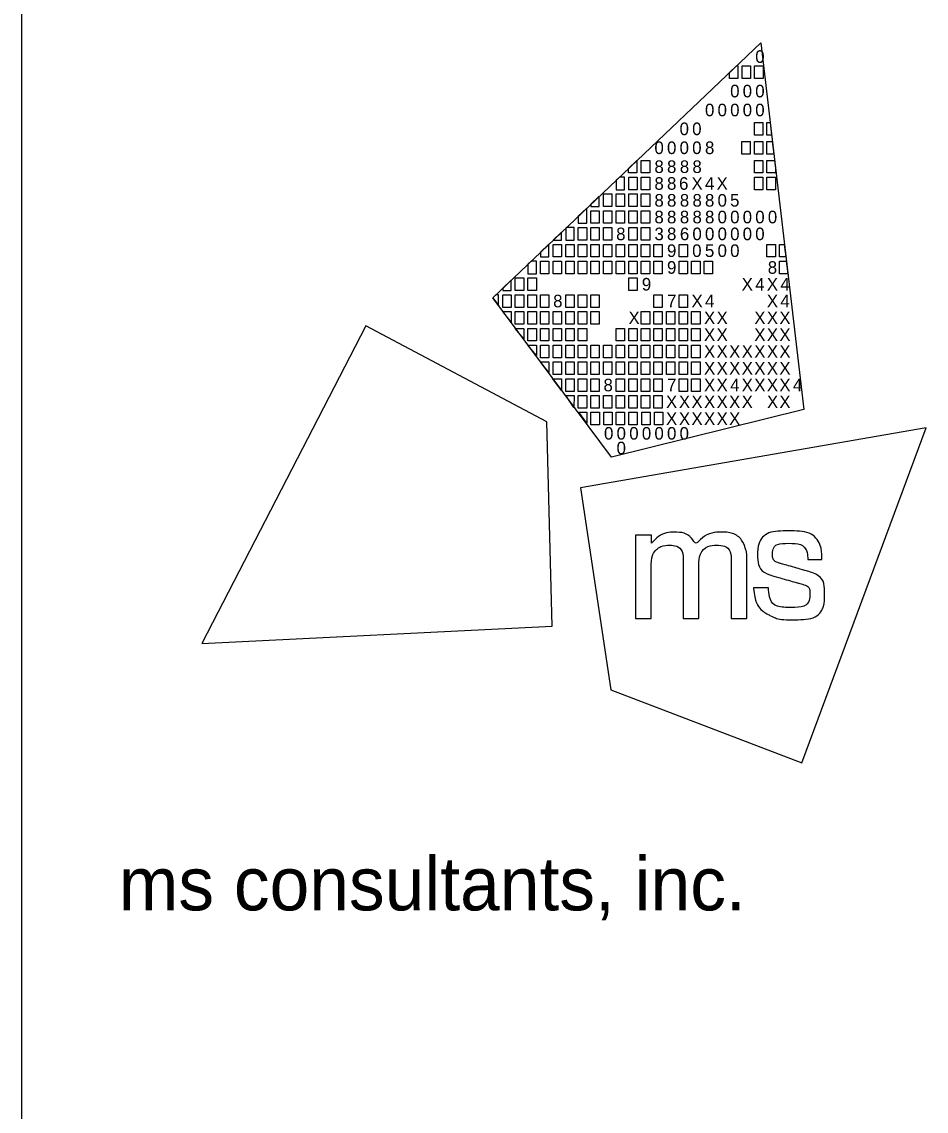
# Model space of a CAD drawing. Extents: x 0 to 34, y 0 to 22.
# Drawn here: x 32 to 33.186, y 2.686 to 4.114 of the extents above; entities that cross this region are included whole.
import ezdxf

# ---------------------------------------------------------------- set-up
doc = ezdxf.new("R2010")
doc.units = 0
doc.layers.add('SH_Border', color=7, linetype='Continuous')
doc.layers.add('SH_Data', color=7, linetype='Continuous')

msp = doc.modelspace()

# ---------------------------------------------------------------- linework, layer by layer
at = {"layer": 'SH_Border'}
for p, q in [((32, 0.5), (32, 21.5)), ((32.6175, 3.7519), (32.9688, 4.0861)), ((32.9688, 4.0861), (32.9688, 4.0861)), ((32.9688, 4.0861), (33.0253, 3.6052)), ((32.773, 3.543), (32.6175, 3.7519)), ((33.0253, 3.6052), (32.773, 3.543))]:
    msp.add_line(p, q, dxfattribs=at)
for points in [[(32.9279, 4.0472), (32.9369, 4.0558), (32.9389, 4.0558), (32.9389, 4.0393), (32.9279, 4.0393)], [(32.9444, 4.0558), (32.9554, 4.0558), (32.9554, 4.0393), (32.9444, 4.0393)], [(32.9609, 4.0558), (32.9719, 4.0558), (32.9719, 4.0393), (32.9609, 4.0393)], [(32.9606, 3.9815), (32.9716, 3.9815), (32.9716, 3.965), (32.9606, 3.965)], [(32.9771, 3.9815), (32.9811, 3.9815), (32.983, 3.965), (32.9771, 3.965)], [(32.9441, 3.9567), (32.9551, 3.9567), (32.9551, 3.9402), (32.9441, 3.9402)], [(32.9606, 3.9567), (32.9716, 3.9567), (32.9716, 3.9402), (32.9606, 3.9402)], [(32.9771, 3.9567), (32.984, 3.9567), (32.9859, 3.9402), (32.9771, 3.9402)], [(32.7953, 3.9211), (32.8064, 3.9316), (32.8064, 3.9154), (32.7953, 3.9154)], [(32.8123, 3.9319), (32.8233, 3.9319), (32.8233, 3.9154), (32.8123, 3.9154)], [(32.9606, 3.9319), (32.9716, 3.9319), (32.9716, 3.9154), (32.9606, 3.9154)], [(32.9771, 3.9319), (32.9869, 3.9319), (32.9881, 3.9218), (32.9881, 3.9154), (32.9771, 3.9154)], [(32.7958, 3.9099), (32.8068, 3.9099), (32.8068, 3.8934), (32.7958, 3.8934)], [(32.8123, 3.9099), (32.8233, 3.9099), (32.8233, 3.8934), (32.8123, 3.8934)], [(32.9606, 3.9099), (32.9716, 3.9099), (32.9716, 3.8934), (32.9606, 3.8934)], [(32.9771, 3.9099), (32.9881, 3.9099), (32.9881, 3.8934), (32.9771, 3.8934)], [(32.7627, 3.8879), (32.7737, 3.8879), (32.7737, 3.8714), (32.7627, 3.8714)], [(32.7793, 3.8879), (32.7903, 3.8879), (32.7903, 3.8714), (32.7793, 3.8714)], [(32.7958, 3.8879), (32.8068, 3.8879), (32.8068, 3.8714), (32.7958, 3.8714)], [(32.8123, 3.8879), (32.8233, 3.8879), (32.8233, 3.8714), (32.8123, 3.8714)], [(32.7462, 3.8659), (32.7572, 3.8659), (32.7572, 3.8494), (32.7462, 3.8494)], [(32.7627, 3.8659), (32.7737, 3.8659), (32.7737, 3.8494), (32.7627, 3.8494)], [(32.7793, 3.8659), (32.7903, 3.8659), (32.7903, 3.8494), (32.7793, 3.8494)], [(32.7958, 3.8659), (32.8068, 3.8659), (32.8068, 3.8494), (32.7958, 3.8494)], [(32.8123, 3.8659), (32.8233, 3.8659), (32.8233, 3.8494), (32.8123, 3.8494)], [(32.7297, 3.8439), (32.7407, 3.8439), (32.7407, 3.8273), (32.7297, 3.8273)], [(32.7462, 3.8439), (32.7572, 3.8439), (32.7572, 3.8273), (32.7462, 3.8273)], [(32.7627, 3.8439), (32.7737, 3.8439), (32.7737, 3.8273), (32.7627, 3.8273)], [(32.7958, 3.8439), (32.8068, 3.8439), (32.8068, 3.8273), (32.7958, 3.8273)], [(32.8123, 3.8439), (32.8233, 3.8439), (32.8233, 3.8273), (32.8123, 3.8273)], [(32.6967, 3.8218), (32.7077, 3.8218), (32.7077, 3.8053), (32.6967, 3.8053)], [(32.7132, 3.8218), (32.7242, 3.8218), (32.7242, 3.8053), (32.7132, 3.8053)], [(32.7297, 3.8218), (32.7407, 3.8218), (32.7407, 3.8053), (32.7297, 3.8053)], [(32.7462, 3.8218), (32.7572, 3.8218), (32.7572, 3.8053), (32.7462, 3.8053)], [(32.7627, 3.8218), (32.7737, 3.8218), (32.7737, 3.8053), (32.7627, 3.8053)], [(32.7793, 3.8218), (32.7903, 3.8218), (32.7903, 3.8053), (32.7793, 3.8053)], [(32.7958, 3.8218), (32.8068, 3.8218), (32.8068, 3.8053), (32.7958, 3.8053)], [(32.8123, 3.8218), (32.8233, 3.8218), (32.8233, 3.8053), (32.8123, 3.8053)], [(32.8288, 3.8218), (32.8398, 3.8218), (32.8398, 3.8053), (32.8288, 3.8053)], [(32.8618, 3.8218), (32.8728, 3.8218), (32.8728, 3.8053), (32.8618, 3.8053)], [(32.9771, 3.8218), (32.9881, 3.8218), (32.9881, 3.8053), (32.9771, 3.8053)], [(32.9935, 3.8218), (32.9998, 3.8218), (33.0018, 3.8053), (32.9935, 3.8053)], [(32.6802, 3.7998), (32.6912, 3.7998), (32.6912, 3.7833), (32.6802, 3.7833)], [(32.6967, 3.7998), (32.7077, 3.7998), (32.7077, 3.7833), (32.6967, 3.7833)], [(32.7132, 3.7998), (32.7242, 3.7998), (32.7242, 3.7833), (32.7132, 3.7833)], [(32.7297, 3.7998), (32.7407, 3.7998), (32.7407, 3.7833), (32.7297, 3.7833)], [(32.7462, 3.7998), (32.7572, 3.7998), (32.7572, 3.7833), (32.7462, 3.7833)], [(32.7627, 3.7998), (32.7737, 3.7998), (32.7737, 3.7833), (32.7627, 3.7833)], [(32.7793, 3.7998), (32.7903, 3.7998), (32.7903, 3.7833), (32.7793, 3.7833)], [(32.7958, 3.7998), (32.8068, 3.7998), (32.8068, 3.7833), (32.7958, 3.7833)], [(32.8123, 3.7998), (32.8233, 3.7998), (32.8233, 3.7833), (32.8123, 3.7833)], [(32.8288, 3.7998), (32.8398, 3.7998), (32.8398, 3.7833), (32.8288, 3.7833)], [(32.8618, 3.7998), (32.8728, 3.7998), (32.8728, 3.7833), (32.8618, 3.7833)], [(32.8783, 3.7998), (32.8893, 3.7998), (32.8893, 3.7833), (32.8783, 3.7833)], [(32.8947, 3.7998), (32.9057, 3.7998), (32.9057, 3.7833), (32.8947, 3.7833)], [(32.9935, 3.7998), (33.0024, 3.7998), (33.0044, 3.7833), (32.9935, 3.7833)], [(32.6471, 3.7778), (32.6581, 3.7778), (32.6581, 3.7613), (32.6471, 3.7613)], [(32.6637, 3.7778), (32.6747, 3.7778), (32.6747, 3.7613), (32.6637, 3.7613)], [(32.7958, 3.7778), (32.8068, 3.7778), (32.8068, 3.7613), (32.7958, 3.7613)], [(32.6306, 3.7558), (32.6416, 3.7558), (32.6416, 3.7393), (32.6306, 3.7393)], [(32.6471, 3.7558), (32.6581, 3.7558), (32.6581, 3.7393), (32.6471, 3.7393)], [(32.6637, 3.7558), (32.6747, 3.7558), (32.6747, 3.7393), (32.6637, 3.7393)], [(32.6802, 3.7558), (32.6912, 3.7558), (32.6912, 3.7393), (32.6802, 3.7393)], [(32.7132, 3.7558), (32.7242, 3.7558), (32.7242, 3.7393), (32.7132, 3.7393)], [(32.7297, 3.7558), (32.7407, 3.7558), (32.7407, 3.7393), (32.7297, 3.7393)], [(32.7462, 3.7558), (32.7572, 3.7558), (32.7572, 3.7393), (32.7462, 3.7393)], [(32.8288, 3.7558), (32.8398, 3.7558), (32.8398, 3.7393), (32.8288, 3.7393)], [(32.8618, 3.7558), (32.8728, 3.7558), (32.8728, 3.7393), (32.8618, 3.7393)], [(32.6306, 3.7338), (32.6416, 3.7338), (32.6416, 3.72)], [(32.6471, 3.7338), (32.6581, 3.7338), (32.6581, 3.7173), (32.6471, 3.7173)], [(32.6637, 3.7338), (32.6747, 3.7338), (32.6747, 3.7173), (32.6637, 3.7173)], [(32.6802, 3.7338), (32.6912, 3.7338), (32.6912, 3.7173), (32.6802, 3.7173)], [(32.6967, 3.7338), (32.7077, 3.7338), (32.7077, 3.7173), (32.6967, 3.7173)], [(32.7132, 3.7338), (32.7242, 3.7338), (32.7242, 3.7173), (32.7132, 3.7173)], [(32.7297, 3.7338), (32.7407, 3.7338), (32.7407, 3.7173), (32.7297, 3.7173)], [(32.7462, 3.7338), (32.7572, 3.7338), (32.7572, 3.7173), (32.7462, 3.7173)], [(32.8123, 3.7338), (32.8233, 3.7338), (32.8233, 3.7173), (32.8123, 3.7173)], [(32.8288, 3.7338), (32.8398, 3.7338), (32.8398, 3.7173), (32.8288, 3.7173)], [(32.8453, 3.7338), (32.8563, 3.7338), (32.8563, 3.7173), (32.8453, 3.7173)], [(32.8618, 3.7338), (32.8728, 3.7338), (32.8728, 3.7173), (32.8618, 3.7173)], [(32.8783, 3.7338), (32.8893, 3.7338), (32.8893, 3.7173), (32.8783, 3.7173)], [(32.6471, 3.7117), (32.6581, 3.7117), (32.6581, 3.698)], [(32.6637, 3.7117), (32.6747, 3.7117), (32.6747, 3.6952), (32.6637, 3.6952)], [(32.6802, 3.7117), (32.6912, 3.7117), (32.6912, 3.6952), (32.6802, 3.6952)], [(32.6967, 3.7117), (32.7077, 3.7117), (32.7077, 3.6952), (32.6967, 3.6952)], [(32.7132, 3.7117), (32.7242, 3.7117), (32.7242, 3.6952), (32.7132, 3.6952)], [(32.7297, 3.7117), (32.7407, 3.7117), (32.7407, 3.6952), (32.7297, 3.6952)], [(32.7793, 3.7117), (32.7903, 3.7117), (32.7903, 3.6952), (32.7793, 3.6952)], [(32.7958, 3.7117), (32.8068, 3.7117), (32.8068, 3.6952), (32.7958, 3.6952)], [(32.8123, 3.7117), (32.8233, 3.7117), (32.8233, 3.6952), (32.8123, 3.6952)], [(32.8288, 3.7117), (32.8398, 3.7117), (32.8398, 3.6952), (32.8288, 3.6952)], [(32.8453, 3.7117), (32.8563, 3.7117), (32.8563, 3.6952), (32.8453, 3.6952)], [(32.8618, 3.7117), (32.8728, 3.7117), (32.8728, 3.6952), (32.8618, 3.6952)], [(32.8783, 3.7117), (32.8893, 3.7117), (32.8893, 3.6952), (32.8783, 3.6952)], [(32.6637, 3.6897), (32.6747, 3.6897), (32.6747, 3.676)], [(32.6747, 3.6897), (32.6747, 3.6897), (32.6747, 3.6897)], [(32.6802, 3.6897), (32.6912, 3.6897), (32.6912, 3.6732), (32.6802, 3.6732)], [(32.6967, 3.6897), (32.7077, 3.6897), (32.7077, 3.6732), (32.6967, 3.6732)], [(32.7132, 3.6897), (32.7242, 3.6897), (32.7242, 3.6732), (32.7132, 3.6732)], [(32.7297, 3.6897), (32.7407, 3.6897), (32.7407, 3.6732), (32.7297, 3.6732)], [(32.7462, 3.6897), (32.7572, 3.6897), (32.7572, 3.6732), (32.7462, 3.6732)], [(32.7627, 3.6897), (32.7737, 3.6897), (32.7737, 3.6732), (32.7627, 3.6732)], [(32.7793, 3.6897), (32.7903, 3.6897), (32.7903, 3.6732), (32.7793, 3.6732)], [(32.7958, 3.6897), (32.8068, 3.6897), (32.8068, 3.6732), (32.7958, 3.6732)], [(32.8123, 3.6897), (32.8233, 3.6897), (32.8233, 3.6732), (32.8123, 3.6732)], [(32.8288, 3.6897), (32.8398, 3.6897), (32.8398, 3.6732), (32.8288, 3.6732)], [(32.8453, 3.6897), (32.8563, 3.6897), (32.8563, 3.6732), (32.8453, 3.6732)], [(32.8618, 3.6897), (32.8728, 3.6897), (32.8728, 3.6732), (32.8618, 3.6732)], [(32.8783, 3.6897), (32.8893, 3.6897), (32.8893, 3.6732), (32.8783, 3.6732)], [(32.6802, 3.6677), (32.6912, 3.6677), (32.6912, 3.654)], [(32.6967, 3.6677), (32.7077, 3.6677), (32.7077, 3.6512), (32.6967, 3.6512)], [(32.7132, 3.6677), (32.7242, 3.6677), (32.7242, 3.6512), (32.7132, 3.6512)], [(32.7297, 3.6677), (32.7407, 3.6677), (32.7407, 3.6512), (32.7297, 3.6512)], [(32.7462, 3.6677), (32.7572, 3.6677), (32.7572, 3.6512), (32.7462, 3.6512)], [(32.7627, 3.6677), (32.7737, 3.6677), (32.7737, 3.6512), (32.7627, 3.6512)], [(32.7793, 3.6677), (32.7903, 3.6677), (32.7903, 3.6512), (32.7793, 3.6512)], [(32.7958, 3.6677), (32.8068, 3.6677), (32.8068, 3.6512), (32.7958, 3.6512)], [(32.8123, 3.6677), (32.8233, 3.6677), (32.8233, 3.6512), (32.8123, 3.6512)], [(32.8288, 3.6677), (32.8398, 3.6677), (32.8398, 3.6512), (32.8288, 3.6512)], [(32.8453, 3.6677), (32.8563, 3.6677), (32.8563, 3.6512), (32.8453, 3.6512)], [(32.8618, 3.6677), (32.8728, 3.6677), (32.8728, 3.6512), (32.8618, 3.6512)], [(32.8783, 3.6677), (32.8893, 3.6677), (32.8893, 3.6512), (32.8783, 3.6512)], [(32.7077, 3.6305), (32.6965, 3.6457), (32.7077, 3.6457)], [(32.7132, 3.6457), (32.7242, 3.6457), (32.7242, 3.6292), (32.7132, 3.6292)], [(32.7297, 3.6457), (32.7407, 3.6457), (32.7407, 3.6292), (32.7297, 3.6292)], [(32.7462, 3.6457), (32.7572, 3.6457), (32.7572, 3.6292), (32.7462, 3.6292)], [(32.7793, 3.6457), (32.7903, 3.6457), (32.7903, 3.6292), (32.7793, 3.6292)], [(32.7958, 3.6457), (32.8068, 3.6457), (32.8068, 3.6292), (32.7958, 3.6292)], [(32.8123, 3.6457), (32.8233, 3.6457), (32.8233, 3.6292), (32.8123, 3.6292)], [(32.8288, 3.6457), (32.8398, 3.6457), (32.8398, 3.6292), (32.8288, 3.6292)], [(32.8618, 3.6457), (32.8728, 3.6457), (32.8728, 3.6292), (32.8618, 3.6292)], [(32.8783, 3.6457), (32.8893, 3.6457), (32.8893, 3.6292), (32.8783, 3.6292)], [(32.724, 3.6082), (32.7132, 3.6237), (32.7242, 3.6237)], [(32.7297, 3.6237), (32.7407, 3.6237), (32.7407, 3.6072), (32.7297, 3.6072)], [(32.7462, 3.6237), (32.7572, 3.6237), (32.7572, 3.6072), (32.7462, 3.6072)], [(32.7627, 3.6237), (32.7737, 3.6237), (32.7737, 3.6072), (32.7627, 3.6072)], [(32.7793, 3.6237), (32.7903, 3.6237), (32.7903, 3.6072), (32.7793, 3.6072)], [(32.7958, 3.6237), (32.8068, 3.6237), (32.8068, 3.6072), (32.7958, 3.6072)], [(32.8123, 3.6237), (32.8233, 3.6237), (32.8233, 3.6072), (32.8123, 3.6072)], [(32.8288, 3.6237), (32.8398, 3.6237), (32.8398, 3.6072), (32.8288, 3.6072)], [(32.7302, 3.6017), (32.7407, 3.6017), (32.7408, 3.5875)], [(32.7463, 3.6017), (32.7573, 3.6017), (32.7573, 3.5852), (32.7463, 3.5852)], [(32.763, 3.6017), (32.774, 3.6017), (32.774, 3.5852), (32.763, 3.5852)], [(32.7794, 3.6017), (32.7904, 3.6017), (32.7904, 3.5852), (32.7794, 3.5852)], [(32.796, 3.6017), (32.807, 3.6017), (32.807, 3.5852), (32.796, 3.5852)], [(32.8129, 3.6017), (32.8239, 3.6017), (32.8239, 3.5851), (32.8129, 3.5851)], [(32.8296, 3.6017), (32.8406, 3.6017), (32.8406, 3.5851), (32.8296, 3.5851)]]:
    msp.add_lwpolyline(points, close=True, dxfattribs=at)
for points in [[(32.7903, 3.9099), (32.7836, 3.9099), (32.7793, 3.9058), (32.7793, 3.8934), (32.7903, 3.8934), (32.7903, 3.9099)], [(32.7572, 3.8849), (32.7462, 3.8744), (32.7462, 3.8714), (32.7572, 3.8714), (32.7572, 3.8849)], [(32.7407, 3.8691), (32.7297, 3.8587), (32.7297, 3.8494), (32.7407, 3.8494), (32.7407, 3.8691)], [(32.7242, 3.8439), (32.7141, 3.8439), (32.7132, 3.843), (32.7132, 3.8273), (32.7242, 3.8273), (32.7242, 3.8439)], [(32.7077, 3.8377), (32.6968, 3.8273), (32.7077, 3.8273), (32.7077, 3.8377)], [(32.6912, 3.822), (32.6802, 3.8115), (32.6802, 3.8053), (32.6912, 3.8053), (32.6912, 3.822)], [(32.6747, 3.7998), (32.6679, 3.7998), (32.6637, 3.7958), (32.6637, 3.7833), (32.6747, 3.7833), (32.6747, 3.7998)], [(32.6416, 3.7749), (32.6306, 3.7644), (32.6306, 3.7613), (32.6416, 3.7613), (32.6416, 3.7749)], [(32.6251, 3.7558), (32.6216, 3.7558), (32.6175, 3.7519), (32.6251, 3.7417), (32.6251, 3.7558)], [(32.4512, 3.7149), (32.2359, 3.2988), (32.6956, 3.3215), (32.6884, 3.5892), (32.4512, 3.7149)], [(33.0229, 3.1422), (33.1859, 3.5814), (32.7324, 3.5029), (32.7722, 3.2381), (33.0229, 3.1422)]]:
    msp.add_lwpolyline(points, dxfattribs=at)
for points in [[(32.8048, 3.3315), (32.8048, 3.3315), (32.8048, 3.4409), (32.8048, 3.4409), (32.8048, 3.4409), (32.8255, 3.4409), (32.8255, 3.4409), (32.8255, 3.4409), (32.8255, 3.4297), (32.8255, 3.4297), (32.8346, 3.4399), (32.8457, 3.4445), (32.8555, 3.4445), (32.8688, 3.4445), (32.8791, 3.4372), (32.8837, 3.4266), (32.8915, 3.4381), (32.905, 3.4446), (32.9166, 3.4446), (32.9325, 3.4446), (32.9451, 3.435), (32.9494, 3.4213), (32.9494, 3.4212), (32.9494, 3.4212), (32.9494, 3.4212), (32.9501, 3.419), (32.9506, 3.4172), (32.9506, 3.4071), (32.9506, 3.4071), (32.9506, 3.3314), (32.9506, 3.3314), (32.9506, 3.3314), (32.9303, 3.3314), (32.9303, 3.3314), (32.9303, 3.3314), (32.9303, 3.4048), (32.9303, 3.4048), (32.9303, 3.4201), (32.9219, 3.4274), (32.911, 3.4274), (32.8995, 3.4274), (32.8879, 3.4171), (32.8879, 3.4001), (32.8879, 3.4001), (32.8879, 3.3315), (32.8879, 3.3315), (32.8879, 3.3315), (32.8674, 3.3315), (32.8674, 3.3315), (32.8674, 3.3315), (32.8674, 3.4059), (32.8674, 3.4059), (32.8674, 3.4203), (32.8588, 3.4274), (32.8496, 3.4274), (32.8384, 3.4274), (32.8254, 3.417), (32.8254, 3.3962), (32.8254, 3.3962), (32.8254, 3.3315), (32.8254, 3.3315), (32.8254, 3.3315), (32.8048, 3.3315), (32.8048, 3.3315)], [(32.9595, 3.3709), (32.9595, 3.3709), (32.9595, 3.3717), (32.9595, 3.3717), (32.9595, 3.3717), (32.9603, 3.3717), (32.9603, 3.3717), (32.9603, 3.3717), (32.9783, 3.3717), (32.9783, 3.3717), (32.9783, 3.3717), (32.9789, 3.3717), (32.9789, 3.3717), (32.9789, 3.3717), (32.979, 3.371), (32.979, 3.371), (32.9803, 3.3554), (32.9887, 3.346), (33.009, 3.346), (33.0273, 3.346), (33.0333, 3.3554), (33.0333, 3.3631), (33.0333, 3.3732), (33.0256, 3.3758), (33.0175, 3.378), (33.0175, 3.378), (32.987, 3.3867), (32.987, 3.3867), (32.972, 3.3909), (32.9648, 3.4019), (32.9648, 3.4142), (32.9648, 3.4303), (32.9768, 3.4462), (33.0052, 3.4462), (33.0348, 3.4462), (33.0489, 3.4285), (33.0489, 3.4095), (33.0489, 3.4095), (33.0489, 3.4087), (33.0489, 3.4087), (33.0489, 3.4087), (33.0482, 3.4087), (33.0482, 3.4087), (33.0482, 3.4087), (33.0312, 3.4087), (33.0312, 3.4087), (33.0312, 3.4087), (33.0305, 3.4087), (33.0305, 3.4087), (33.0305, 3.4087), (33.0305, 3.4094), (33.0305, 3.4094), (33.0301, 3.4208), (33.0226, 3.43), (33.0056, 3.43), (32.9891, 3.43), (32.9843, 3.4218), (32.9843, 3.4157), (32.9843, 3.4108), (32.9869, 3.4059), (32.9959, 3.4033), (32.9959, 3.4033), (33.0255, 3.3948), (33.0255, 3.3948), (33.0462, 3.3889), (33.0527, 3.3777), (33.0527, 3.3639), (33.0527, 3.3462), (33.041, 3.3298), (33.0087, 3.3298), (32.9952, 3.3298), (32.9877, 3.3321), (32.9823, 3.3348), (32.969, 3.3414), (32.9609, 3.3536), (32.9595, 3.3709)]]:
    msp.add_open_spline(points, degree=3, dxfattribs=at)
at = {"layer": 'SH_Data'}
msp.add_line((32.75, 3.5), (32.75, 3.5), dxfattribs=at)

# ---------------------------------------------------------------- texts
at = {"layer": 'SH_Border'}
for s, height, p in [('0', 0.0165, (32.9617, 4.0597)), ('0', 0.0165, (32.9288, 4.0145)), ('0', 0.0165, (32.9452, 4.0145)), ('0', 0.0165, (32.9617, 4.0145)), ('0', 0.0165, (32.8958, 3.9897)), ('0', 0.0165, (32.9123, 3.9897)), ('0', 0.0165, (32.9288, 3.9897)), ('0', 0.0165, (32.9452, 3.9897)), ('0', 0.0165, (32.9617, 3.9897)), ('0', 0.0165, (32.8625, 3.965)), ('0', 0.0165, (32.879, 3.965)), ('0', 0.0165, (32.8295, 3.9402)), ('0', 0.0165, (32.846, 3.9402)), ('0', 0.0165, (32.8625, 3.9402)), ('0', 0.0165, (32.879, 3.9402)), ('8', 0.0165, (32.8958, 3.9402)), ('8', 0.0165, (32.8295, 3.9154)), ('8', 0.0165, (32.846, 3.9154)), ('8', 0.0165, (32.8628, 3.9154)), ('8', 0.0165, (32.8793, 3.9154)), ('8', 0.0165, (32.8295, 3.8934)), ('8', 0.0165, (32.846, 3.8934)), ('6', 0.0165, (32.8618, 3.8934)), ('X', 0.0165, (32.8781, 3.8934)), ('4', 0.0165, (32.8958, 3.8934)), ('X', 0.0165, (32.911, 3.8934)), ('8', 0.0165, (32.8295, 3.8713)), ('8', 0.0165, (32.846, 3.8713)), ('8', 0.0165, (32.8628, 3.8713)), ('8', 0.0165, (32.8794, 3.8713)), ('8', 0.0165, (32.8958, 3.8713)), ('0', 0.0165, (32.9123, 3.8713)), ('5', 0.0165, (32.9287, 3.8713)), ('8', 0.0165, (32.8295, 3.8494)), ('8', 0.0165, (32.846, 3.8494)), ('8', 0.0165, (32.8628, 3.8494)), ('8', 0.0165, (32.8794, 3.8494)), ('8', 0.0165, (32.8958, 3.8494)), ('0', 0.0165, (32.9123, 3.8494)), ('0', 0.0165, (32.9288, 3.8494)), ('0', 0.0165, (32.9452, 3.8494)), ('0', 0.0165, (32.9617, 3.8494)), ('0', 0.0165, (32.9782, 3.8494)), ('8', 0.0165, (32.7793, 3.8273)), ('3', 0.0165, (32.8295, 3.8273)), ('8', 0.0165, (32.846, 3.8273)), ('6', 0.0165, (32.8629, 3.8273)), ('0', 0.0165, (32.8793, 3.8273)), ('0', 0.0165, (32.8958, 3.8273)), ('0', 0.0165, (32.9123, 3.8273)), ('0', 0.0165, (32.9288, 3.8273)), ('0', 0.0165, (32.9452, 3.8273)), ('0', 0.0165, (32.9617, 3.8273)), ('9', 0.0165, (32.846, 3.8053)), ('0', 0.0165, (32.879, 3.8053)), ('5', 0.0165, (32.8957, 3.8053)), ('0', 0.0165, (32.9123, 3.8053)), ('0', 0.0165, (32.9288, 3.8053)), ('9', 0.0165, (32.846, 3.7833)), ('8', 0.0165, (32.9781, 3.7833)), ('9', 0.0165, (32.813, 3.7613)), ('X', 0.0165, (32.9439, 3.7613)), ('4', 0.0165, (32.9617, 3.7613)), ('X', 0.0165, (32.9769, 3.7613)), ('4', 0.0165, (32.9946, 3.7613)), ('8', 0.0165, (32.6967, 3.7393)), ('7', 0.0165, (32.846, 3.7393)), ('X', 0.0165, (32.8781, 3.7393)), ('4', 0.0165, (32.8958, 3.7393)), ('X', 0.0165, (32.9769, 3.7393)), ('4', 0.0165, (32.9946, 3.7393)), ('X', 0.0165, (32.7955, 3.7173)), ('X', 0.0165, (32.8945, 3.7173)), ('X', 0.0165, (32.911, 3.7173)), ('X', 0.0165, (32.9604, 3.7173)), ('X', 0.0165, (32.9769, 3.7173)), ('X', 0.0165, (32.9933, 3.7173)), ('X', 0.0165, (32.8945, 3.6952)), ('X', 0.0165, (32.911, 3.6952)), ('X', 0.0165, (32.9604, 3.6952)), ('X', 0.0165, (32.9769, 3.6952)), ('X', 0.0165, (32.9933, 3.6952)), ('X', 0.0165, (32.8945, 3.6732)), ('X', 0.0165, (32.911, 3.6732)), ('X', 0.0165, (32.9274, 3.6732)), ('X', 0.0165, (32.9439, 3.6732)), ('X', 0.0165, (32.9604, 3.6732)), ('X', 0.0165, (32.9769, 3.6732)), ('X', 0.0165, (32.9933, 3.6732)), ('X', 0.0165, (32.8945, 3.6512)), ('X', 0.0165, (32.911, 3.6512)), ('X', 0.0165, (32.9274, 3.6512)), ('X', 0.0165, (32.9439, 3.6512)), ('X', 0.0165, (32.9604, 3.6512)), ('X', 0.0165, (32.9769, 3.6512)), ('X', 0.0165, (32.9933, 3.6512)), ('8', 0.0165, (32.7627, 3.6292)), ('7', 0.0165, (32.846, 3.6292)), ('X', 0.0165, (32.8945, 3.6292)), ('X', 0.0165, (32.911, 3.6292)), ('4', 0.0165, (32.9288, 3.6292)), ('X', 0.0165, (32.9439, 3.6292)), ('X', 0.0165, (32.9604, 3.6292)), ('X', 0.0165, (32.9769, 3.6292)), ('X', 0.0165, (32.9933, 3.6292)), ('4', 0.0165, (33.0111, 3.6292)), ('X', 0.0165, (32.8447, 3.6072)), ('X', 0.0165, (32.8616, 3.6072)), ('X', 0.0165, (32.878, 3.6072)), ('X', 0.0165, (32.8945, 3.6072)), ('X', 0.0165, (32.911, 3.6072)), ('X', 0.0165, (32.9274, 3.6072)), ('X', 0.0165, (32.9439, 3.6072)), ('X', 0.0165, (32.9771, 3.6072)), ('X', 0.0165, (32.9933, 3.6072)), ('X', 0.0165, (32.8447, 3.5851)), ('X', 0.0165, (32.8616, 3.5851)), ('X', 0.0165, (32.878, 3.5851)), ('X', 0.0165, (32.8945, 3.5851)), ('X', 0.0165, (32.911, 3.5851)), ('X', 0.0165, (32.9274, 3.5851)), ('0', 0.0165, (32.7634, 3.5659)), ('0', 0.0165, (32.7799, 3.5659)), ('0', 0.0165, (32.7965, 3.5659)), ('0', 0.0165, (32.813, 3.5659)), ('0', 0.0165, (32.8295, 3.5659)), ('0', 0.0165, (32.846, 3.5659)), ('0', 0.0165, (32.8625, 3.5659)), ('0', 0.0165, (32.7799, 3.5467)), ('ms consultants, inc.', 0.07, (32.1273, 2.9489))]:
    msp.add_text(s, height=height, rotation=360, dxfattribs=at).set_placement(p)

doc.saveas('drawing.dxf')
